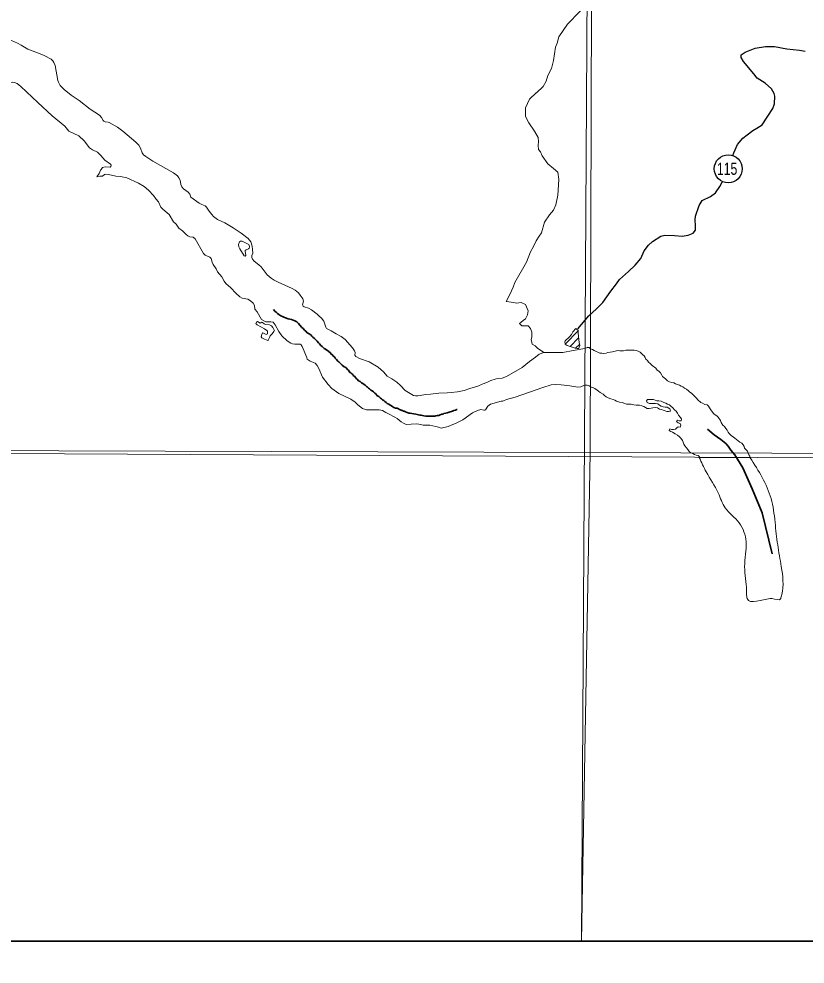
# Model space of a CAD drawing. Extents: x -1643653 to 4543381, y 1624270 to 13878484.
# Drawn here: x 604258 to 608778, y 8895895 to 8901328 of the extents above; entities that cross this region are included whole.
import ezdxf
from ezdxf.enums import TextEntityAlignment as Align

# ---------------------------------------------------------------- set-up
doc = ezdxf.new("R2010")
doc.units = 0
doc.header["$LTSCALE"] = 200
doc.linetypes.add('LONG_DASH_SHORT_DASH', pattern=[9.9, 6, -1.2, 1.5, -1.2])
doc.layers.add('1', color=7, linetype='Continuous', lineweight=13)
doc.layers.add('6', color=7, linetype='Continuous', lineweight=13)

msp = doc.modelspace()

# ---------------------------------------------------------------- linework, layer by layer
at = {"layer": '1', "lineweight": 25}
msp.add_spline([(814781, 9009175.5), (814787.2, 9009173.4), (814796.9, 9009173.4), (814799.4, 9009172.4), (814805.1, 9009174.5), (814805.6, 9009176.5), (814811.7, 9009179.5), (814811.7, 9009179.5), (814801.5, 9009181), (814790.7, 9009181.5), (814784.1, 9009183.1), (814777.4, 9009185.1), (814778.4, 9009175.5)], degree=3, dxfattribs=at)
at = {"layer": '6'}
for p, q in [((607398.2, 8899458.9), (607473.3, 8899534)), ((607427.1, 8899445.4), (607476, 8899494.2)), ((607458.9, 8899434.7), (607481.1, 8899456.9)), ((608462.4, 8898805.8), (608169.4, 8898807.8))]:
    msp.add_line(p, q, dxfattribs=at)
at = {"layer": '6', "lineweight": 35}
msp.add_lwpolyline([(574695.3, 8924769.6), (626625.7, 8924769.6), (626625.7, 8896026.7), (574695.3, 8896026.7)], close=True, dxfattribs=at)
at = {"layer": '6'}
for points in [[(607657.7, 8924743.3), (607574.2, 8909874.9), (607492.3, 8896026.7)], [(607518.6, 8901403.9), (607482.1, 8901370.7), (607412.3, 8901297.6), (607362.4, 8901224.5), (607352.5, 8901188), (607342.5, 8901164.7), (607332.5, 8901088.4), (607319.2, 8901041.9), (607299.3, 8901002), (607289.3, 8900968.8), (607272.7, 8900938.9), (607233.9, 8900903.3)], [(603607.9, 8901202.5), (603628.6, 8901215.9), (603671.7, 8901230.7), (603774.9, 8901247.2), (603862.9, 8901251.2), (603892.8, 8901248.7), (603993.8, 8901227), (604022.6, 8901225.8), (604073.7, 8901229.1), (604097.1, 8901225.2), (604136.5, 8901210.6), (604149.3, 8901209.6), (604198.3, 8901211), (604250.4, 8901188.4), (604270.6, 8901176.9)], [(604270.6, 8901176.9), (604309.9, 8901154.5), (604339.3, 8901141.9), (604370.9, 8901131.4)], [(604370.9, 8901131.4), (604370.9, 8901131.4), (604403.6, 8901117.1), (604442.5, 8901095.2), (604452, 8901087.1), (604458.6, 8901076.9), (604465.4, 8901060), (604482, 8900973.9), (604485.2, 8900964.1), (604495.8, 8900945.5), (604517.3, 8900922.7), (604558.5, 8900888.9), (604603.8, 8900858.4), (604667, 8900809.4), (604720.7, 8900774.8), (604733.1, 8900760.8), (604741.5, 8900744.4), (604745.2, 8900740.3), (604753.2, 8900735.9), (604770.9, 8900734.2), (604776.8, 8900732.2), (604824.3, 8900704.6), (604854.7, 8900681.5), (604929.1, 8900620.1), (604947.7, 8900602.6), (604957.6, 8900585), (604966.3, 8900557.4), (604974.2, 8900547), (604987.4, 8900535.9), (605027.8, 8900510.6), (605147.2, 8900442.4), (605169.2, 8900426.4), (605178, 8900414.5), (605184.6, 8900400), (605189.5, 8900375.3), (605194.2, 8900361.7), (605203.3, 8900351.7), (605231.7, 8900331.2), (605239.8, 8900319.8), (605246.1, 8900303.3), (605294.8, 8900269.1), (605308.7, 8900261.3), (605318.4, 8900257.2)], [(604366, 8900847), (604269.1, 8900939.9), (604248, 8900956), (604232.7, 8900962.7), (604218.8, 8900964.1), (604182.6, 8900956.3), (604161.8, 8900955.6), (604125.6, 8900973.4), (604104.3, 8900978.3), (604083.2, 8900978.5), (604062.8, 8900972.3)], [(607232.8, 8900902.4), (607193, 8900865.8), (607169.7, 8900816), (607169.7, 8900766.2), (607189.6, 8900729.7), (607222.9, 8900683.2), (607242.8, 8900646.7), (607246.1, 8900623.4), (607242.8, 8900600.2), (607246.1, 8900576.9), (607256.1, 8900563.6), (607266.1, 8900540.4), (607299.3, 8900493.9), (607332.5, 8900467.3), (607355.8, 8900447.4), (607362.4, 8900404.2), (607355.8, 8900314.6), (607345.8, 8900258.1), (607332.5, 8900228.2), (607309.3, 8900201.6), (607279.4, 8900158.5), (607262.7, 8900098.7), (607249.5, 8900078.8), (607232.8, 8900052.2), (607216.2, 8900019), (607199.6, 8899989.1), (607176.3, 8899929.3), (607109.9, 8899813.1), (607099.9, 8899786.5), (607080, 8899743.3), (607060, 8899703.5), (607103.2, 8899696.8), (607119.8, 8899693.5), (607146.4, 8899696.8), (607169.7, 8899686.9), (607186.3, 8899650.3), (607183, 8899627.1), (607169.7, 8899603.8), (607156.4, 8899593.9), (607146.4, 8899583.9), (607136.5, 8899577.3), (607149.8, 8899564), (607186.3, 8899564), (607199.6, 8899547.4), (607206.2, 8899527.4), (607206.2, 8899507.5), (607206.2, 8899497.6), (607202.9, 8899484.3), (607206.2, 8899467.7), (607209.6, 8899457.7), (607226.2, 8899447.8), (607239.5, 8899434.5), (607276, 8899411.2)], [(604545.7, 8900683.2), (604522.7, 8900710.9), (604449.6, 8900771.1), (604366, 8900847)], [(604745.3, 8900474.6), (604755.6, 8900477.1), (604782.2, 8900475.7), (604787.1, 8900478.4), (604787.9, 8900487.3), (604784.5, 8900492.2), (604752, 8900515.1), (604729.6, 8900542.8), (604709.4, 8900561), (604681.6, 8900575), (604663.6, 8900587.3), (604633.8, 8900627.5), (604602, 8900655.7), (604545.7, 8900683.2)], [(604706.6, 8900419.8), (604719.1, 8900439.6), (604727.3, 8900457.6), (604729.9, 8900461.2), (604729.9, 8900461.2)], [(604729.9, 8900461.2), (604737.9, 8900472.8), (604745.3, 8900474.6)], [(605045.3, 8900294.2), (605031, 8900312.3), (605003.2, 8900342.6), (604977.4, 8900365.2), (604945.5, 8900383.7), (604877.4, 8900413.4), (604842.3, 8900421.4), (604815.8, 8900423.5), (604773.8, 8900433.3), (604754.4, 8900435.3), (604749.3, 8900433), (604738.7, 8900423.7), (604723, 8900423.6), (604706.6, 8900419.8)], [(605438.8, 8899820.5), (605424.5, 8899844.7), (605400.3, 8899874.5), (605391.9, 8899891.1), (605374.3, 8899916.5), (605368.7, 8899929), (605362.7, 8899950.1), (605355.1, 8899957.3), (605329.3, 8899970.5), (605318.8, 8899978.5), (605271.5, 8900063.6), (605260.1, 8900073.8), (605241.3, 8900075.8), (605228.1, 8900080.5), (605218.7, 8900087.6), (605197.7, 8900109.2), (605177.8, 8900125.6), (605161.6, 8900148.5), (605147.3, 8900162.1), (605121.1, 8900202.5), (605110.9, 8900213.2), (605084.9, 8900233.7), (605074.1, 8900246.2), (605060.1, 8900275.4), (605045.3, 8900294.2)], [(605318.4, 8900257.2), (605328.1, 8900253.2), (605335.8, 8900246.2), (605350.9, 8900222.8), (605366.1, 8900202.7), (605377.3, 8900192.3), (605399.9, 8900175.6), (605442.3, 8900156.2), (605489.3, 8900126.6)], [(605489.3, 8900126.6), (605536.4, 8900097), (605576.3, 8900065.9), (605584, 8900055.8)], [(605584, 8900055.8), (605591.8, 8900045.6), (605599.5, 8900021.8), (605601.3, 8900001.9)], [(605601.3, 8900001.9), (605603.1, 8899982.1), (605597.9, 8899967.5), (605596.6, 8899957), (605600.2, 8899946.1), (605609.6, 8899935.7), (605637, 8899914.4), (605637, 8899914.4), (605649.8, 8899902), (605684.5, 8899857.5), (605707.9, 8899837.1), (605725.2, 8899825.1), (605748.8, 8899814.5)], [(605651.9, 8899599.2), (605627.2, 8899644.2), (605614.9, 8899659.3), (605613, 8899680), (605604.8, 8899694.2), (605588.8, 8899707.8), (605573.8, 8899716.3), (605540.9, 8899723.1), (605528.7, 8899729.8), (605504.9, 8899751.3), (605476.1, 8899781.6), (605446.9, 8899806.9), (605438.8, 8899820.5)], [(605748.8, 8899814.5), (605828.9, 8899778.6), (605845.6, 8899768.4), (605864.6, 8899753.2), (605875.9, 8899739.1)], [(605875.9, 8899739.1), (605887.1, 8899725), (605890.8, 8899718.1), (605893.6, 8899706.3), (605887.9, 8899684.9), (605892.5, 8899676.5), (605897.1, 8899672.9), (605922.3, 8899665.2), (605940.2, 8899656.1), (605972.7, 8899630.7), (605982.6, 8899621.7)], [(605800.4, 8899478.3), (605768.7, 8899506.2), (605752.1, 8899530.8), (605730.5, 8899570.1), (605719.2, 8899583.9), (605706, 8899587.4), (605690.9, 8899586.3), (605677.8, 8899587.4), (605651.9, 8899599.2)], [(605982.6, 8899621.7), (605997.9, 8899607.7), (606011.1, 8899590.2), (606021.8, 8899555.1), (606026.3, 8899548.7), (606053.9, 8899535.2), (606082.6, 8899518.2)], [(605886.8, 8899444.2), (605880.5, 8899454.1), (605875.6, 8899458), (605871.8, 8899459), (605843.6, 8899457.8), (605831.8, 8899459.6), (605821.4, 8899464.6), (605800.4, 8899478.3)], [(606082.6, 8899518.2), (606110.4, 8899501.7), (606133.8, 8899485.1), (606175, 8899438.1), (606188.2, 8899420.1), (606191.5, 8899410.3), (606189.5, 8899394.8), (606194.9, 8899386.7), (606215.6, 8899376.8), (606270.9, 8899356.2), (606324.1, 8899326.3), (606339, 8899313.3)], [(606167, 8899141.3), (606097.8, 8899173.8), (606057.4, 8899203.2), (606036.3, 8899225.7), (606003.4, 8899268.5), (605982, 8899319.3), (605972.7, 8899335.8), (605960.9, 8899348.2), (605932.8, 8899360.8), (605920.3, 8899368.7), (605916, 8899369.4), (605914.2, 8899381.2), (605886.8, 8899444.2)], [(606996.3, 8899256.7), (607009.1, 8899260.5), (607037.2, 8899263), (607061.2, 8899271.7), (607150.5, 8899324.7), (607193.7, 8899358.8), (607228.5, 8899383), (607248.7, 8899401.6), (607276, 8899411.2), (607305.9, 8899411.2), (607385.7, 8899411.2), (607445.5, 8899421.2), (607512.3, 8899432.5)], [(607512.3, 8899432.5), (607525.9, 8899438.3), (607537.1, 8899438.2), (607545.2, 8899432.1), (607555.3, 8899427.9), (607565.5, 8899422.8), (607577.6, 8899416.6), (607586.8, 8899411.4), (607597.9, 8899407.3), (607609.1, 8899406.2), (607621.3, 8899405.1), (607633.5, 8899406), (607643.7, 8899410), (607658, 8899413), (607671.2, 8899413.9), (607701.8, 8899420.9), (607713, 8899420.8), (607723.1, 8899420.7), (607734.3, 8899420.7), (607747.6, 8899424.6), (607757.7, 8899424.6), (607770, 8899424.5), (607783.2, 8899424.4), (607795.4, 8899424.3), (607806.6, 8899422.2), (607817.7, 8899418.1), (607830.9, 8899411.9), (607838, 8899404.7), (607846.1, 8899397.5), (607853.1, 8899390.3)], [(607853.1, 8899390.3), (607858.2, 8899381.2), (607863.2, 8899371.9), (607871.3, 8899363.7), (607878.3, 8899355.6), (607887.4, 8899347.3), (607899.6, 8899336.1), (607919.8, 8899319.6), (607927.8, 8899309.4), (607937, 8899302.2), (607946, 8899293), (607954.1, 8899280.7), (607959.1, 8899271.5), (607975.3, 8899258.1), (607987.4, 8899247.9), (607998.6, 8899242.7), (608011.8, 8899238.6), (608023, 8899235.4), (608033.1, 8899230.3), (608045.3, 8899226.1), (608056.4, 8899222), (608065.6, 8899217.8), (608075.7, 8899212.7), (608085.8, 8899205.5), (608097, 8899199.3), (608108.1, 8899190.1), (608116.2, 8899182.9), (608124.3, 8899176.7), (608135.4, 8899166.4), (608142.5, 8899159.3), (608154.6, 8899148), (608160.6, 8899137.8), (608178.8, 8899123.4), (608189, 8899119.2), (608202.2, 8899112), (608214.3, 8899108.9), (608222.4, 8899101.7), (608228.5, 8899092.5), (608236.5, 8899081.2), (608246.6, 8899067.9), (608252.7, 8899058.7), (608260.8, 8899052.6), (608269.9, 8899046.4), (608279, 8899038.2), (608291, 8899018.7), (608295, 8899007.5), (608306.1, 8898992.2), (608314.2, 8898985), (608322.3, 8898973.7), (608329.3, 8898963.5), (608335.3, 8898953.3), (608342.4, 8898945.1), (608352.5, 8898933.8), (608365.7, 8898923.5), (608374.8, 8898918.4), (608383.9, 8898910.2), (608393, 8898903), (608403.1, 8898895.8), (608414.2, 8898889.6), (608421.3, 8898880.4), (608427.3, 8898870.2), (608430.3, 8898859.9), (608439.4, 8898850.7), (608447.5, 8898843.5), (608451.5, 8898832.3)], [(606339, 8899313.3), (606353.8, 8899300.2), (606375.8, 8899273.6), (606401.3, 8899259.5), (606425.6, 8899243.5), (606430.3, 8899239.2)], [(606430.3, 8899239.2), (606451.1, 8899220.5), (606477.9, 8899191.6), (606526.1, 8899162.9), (606538.8, 8899160.4), (606552.3, 8899160.9), (606564.8, 8899163.4)], [(606850.9, 8899202.7), (606897.3, 8899217.3), (606921.3, 8899228.2), (606948.9, 8899237.7), (606970.8, 8899249.3), (606996.3, 8899256.7)], [(607510.3, 8899223.4), (607489.5, 8899213.8), (607472.3, 8899210.6), (607425.7, 8899218.6), (607376, 8899224.9), (607343.2, 8899226.9), (607318.7, 8899223.8), (607269.6, 8899209.6), (607112, 8899153.1), (607061.6, 8899139.4), (607044.9, 8899132.1), (607038.2, 8899131.2)], [(607965.2, 8899123.7), (607951, 8899129.9), (607937.8, 8899133.1), (607926.6, 8899133.2), (607916.5, 8899137.3), (607906.3, 8899140.4), (607892.1, 8899140.5), (607872.8, 8899140.6), (607866.6, 8899132.5), (607870.6, 8899122.3), (607882.8, 8899117.1), (607894, 8899117.1), (607904.2, 8899117), (607917.4, 8899116.9), (607930.6, 8899115.8), (607940.7, 8899107.6), (607950.8, 8899101.4), (607963, 8899097.3), (607974.2, 8899096.2), (607984.4, 8899096.1), (607999.6, 8899085.8), (608003.5, 8899073.6), (607993.3, 8899070.6), (607983.2, 8899070.6), (607973, 8899074.8), (607961.9, 8899078.9), (607952.7, 8899083.1), (607941.6, 8899084.2), (607930.4, 8899092.4), (607917.2, 8899093.5), (607903, 8899092.6), (607892.8, 8899089.6), (607881.6, 8899088.6), (607870.4, 8899088.7), (607861.3, 8899093.8), (607850.1, 8899100), (607840, 8899104.2), (607826.8, 8899108.3), (607816.6, 8899108.4), (607806.4, 8899108.4), (607793.2, 8899109.6), (607778, 8899112.7), (607763.7, 8899113.8), (607751.5, 8899113.9), (607741.4, 8899118), (607727.2, 8899122.2), (607712, 8899125.3), (607693.7, 8899131.6), (607684.6, 8899136.7), (607674.4, 8899139.9), (607661.2, 8899144), (607646, 8899150.2), (607634.8, 8899155.4), (607625.7, 8899163.6), (607617.7, 8899170.8), (607600.4, 8899180.1), (607591.3, 8899188.3), (607583.2, 8899194.4), (607569.1, 8899203.7), (607557.9, 8899208.9), (607547.8, 8899212), (607536.6, 8899218.2), (607525.4, 8899222.3), (607515.3, 8899222.4), (607510.3, 8899223.4)], [(606564.8, 8899163.4), (606594.8, 8899169.2), (606624, 8899170.2), (606673, 8899176.3), (606719.7, 8899178.1), (606743.5, 8899180.8)], [(606743.5, 8899180.8), (606780.2, 8899185.1), (606817.4, 8899192.1), (606850.9, 8899202.7)], [(606368.4, 8899065.7), (606348.9, 8899077), (606329, 8899080.2), (606255.6, 8899080.9), (606233.8, 8899088.8), (606207, 8899108.8), (606191.6, 8899125.1), (606167, 8899141.3)], [(607038.2, 8899131.2), (607030.1, 8899130.2), (606968.5, 8899113.9), (606953.5, 8899101.6), (606940.8, 8899080.5), (606936.9, 8899079.8)], [(608076.6, 8898895.8), (608072.6, 8898905), (608064.5, 8898918.3), (608056.4, 8898925.5), (608045.3, 8898934.7), (608031.1, 8898943), (608015.9, 8898952.2), (608006.8, 8898956.4), (607996.7, 8898961.5), (607999.8, 8898971.7), (608011, 8898968.6), (608022.1, 8898968.5), (608032.3, 8898969.5), (608040.5, 8898976.5), (608048.7, 8898982.6), (608060.9, 8898981.5), (608064, 8898992.7), (608059, 8899001.9), (608048.8, 8899007.1), (608039.7, 8899013.2), (608043.9, 8899022.4), (608054, 8899017.2), (608066.2, 8899017.1), (608067.3, 8899029.3), (608059.2, 8899038.6), (608051.2, 8899049.8), (608044.1, 8899061.1), (608036.1, 8899072.3), (608027, 8899080.5), (608017.9, 8899092.8), (608005.8, 8899102.1), (607997.7, 8899110.3), (607987.5, 8899113.4), (607977.4, 8899119.6), (607965.2, 8899123.7)], [(606669.7, 8898980.5), (606654.6, 8898985.8), (606620, 8898992.5), (606583.1, 8898992.2), (606556.5, 8898999.1), (606542.7, 8899000.4), (606485.3, 8898997.2), (606468.8, 8899003.8), (606455.3, 8899011.8), (606432, 8899031.1), (606419.7, 8899039.2), (606382.7, 8899057.4), (606368.4, 8899065.7)], [(606936.9, 8899079.8), (606931.9, 8899079.1), (606913.4, 8899083.4), (606894.4, 8899077.1), (606866.6, 8899063), (606810.7, 8899023.7), (606776, 8899005.8), (606726.3, 8898985.3), (606684.8, 8898975.2), (606669.7, 8898980.5)], [(574695.3, 8898953.2), (596544.3, 8898870.4), (626625.7, 8898710.8)], [(608169.4, 8898807.8), (608170.6, 8898811.7), (608162.5, 8898818.9), (608151.3, 8898821), (608142.2, 8898825.1), (608132.1, 8898829.2), (608120.9, 8898833.4), (608110.8, 8898841.6), (608104.8, 8898852.9), (608096.7, 8898862.1), (608087.6, 8898873.3), (608081.6, 8898882.6), (608076.6, 8898895.8)], [(608451.5, 8898832.3), (608454.5, 8898822.1), (608460.5, 8898813.9), (608462.4, 8898805.8), (608169.4, 8898807.8)]]:
    msp.add_lwpolyline(points, dxfattribs=at)
for points in [[(618535.2, 8909853.3), (607574.3, 8909890.7), (607543.3, 8898835.3), (618504.2, 8898795.8)], [(605578, 8900006.4), (605581.1, 8900009.7), (605583.1, 8900017.2), (605581.8, 8900027.9), (605579.6, 8900031.9), (605553.8, 8900045.2), (605540.6, 8900049.4), (605532.2, 8900049.6), (605526.5, 8900045.7), (605520.9, 8900031.3), (605522.3, 8900018.3), (605527.3, 8900006.6), (605552.8, 8899966.1), (605559, 8899963.9), (605562.7, 8899968.7), (605558.6, 8899992.7), (605559.4, 8899996.8), (605563.9, 8900000.6)], [(605726.5, 8899537.9), (605724, 8899530.6), (605714.4, 8899518.2), (605703, 8899506.1), (605697.8, 8899496.6), (605691.8, 8899481.5), (605690, 8899479.8), (605670.7, 8899486.1), (605654.2, 8899494.3), (605651.4, 8899501.1), (605654.2, 8899514.3), (605658.7, 8899522.5), (605659.8, 8899523), (605664.4, 8899521.9), (605680, 8899513.5), (605686.4, 8899518), (605687.1, 8899532.4), (605682.6, 8899537.5), (605669, 8899546.2), (605627.1, 8899569.7), (605621, 8899577.3), (605624.1, 8899584.8), (605629.5, 8899588.5), (605644.9, 8899579.4), (605648.7, 8899580.6), (605650.3, 8899583.7), (605653.3, 8899585.6), (605658.1, 8899583.4), (605667.7, 8899575.2), (605676.3, 8899570.6), (605698.8, 8899568.8), (605709.7, 8899562.8), (605717.5, 8899553.2), (605726.3, 8899538.9)], [(607460.5, 8899548.4), (607473.4, 8899537.4), (607473.1, 8899520.7), (607479, 8899466.9), (607482.5, 8899450.2), (607481.5, 8899443.7), (607477.8, 8899435.1), (607475, 8899432.4), (607467.5, 8899432.5), (607456.8, 8899435.3), (607411.1, 8899450.8), (607397.8, 8899459.1), (607396.2, 8899472.7), (607398.9, 8899476.5), (607421.7, 8899498.1), (607434.4, 8899514.6), (607443.2, 8899529)], [(596544.3, 8898870.4), (596531.7, 8896026.7), (607492.3, 8896026.7), (607543.3, 8898835.3)]]:
    msp.add_lwpolyline(points, close=True, dxfattribs=at)
at = {"layer": '6', "lineweight": 25}
for points in [[(608362.5, 8900541.9), (608368.2, 8900558.4), (608389.8, 8900605.2), (608420.5, 8900642.9), (608446, 8900662.2), (608477.7, 8900686.6), (608500.2, 8900699.8), (608531.8, 8900719.1), (608592.3, 8900811.7), (608601.6, 8900840.2), (608604.8, 8900883), (608599.7, 8900899.3), (608584.6, 8900924.8), (608548, 8900957.4), (608502.2, 8900986.1), (608484, 8901011.6), (608424.2, 8901083), (608411, 8901106.4), (608410, 8901120.7), (608433.5, 8901137), (608490.7, 8901160.3), (608550.8, 8901168.3), (608602.8, 8901168.2), (608674, 8901155.9), (608745.3, 8901147.6), (608778.9, 8901141.4)], [(607472.2, 8899545.8), (607534.4, 8899621.6), (607579.4, 8899661.2), (607616.2, 8899696.8), (607661.2, 8899761.9), (607694, 8899804.7), (607711.4, 8899829.1), (607763.6, 8899875.9), (607801.4, 8899912.5), (607833.1, 8899950.1), (607852.6, 8899993.9), (607877.2, 8900026.4), (607900.7, 8900048.8), (607948.7, 8900079.3), (607972.2, 8900084.3), (608027.2, 8900083.2), (608072, 8900078.1), (608106.7, 8900084.1), (608135.2, 8900096.3), (608147.5, 8900113.6), (608148.6, 8900139), (608146.7, 8900173.7), (608147.8, 8900194.1), (608168.4, 8900255.2), (608186.9, 8900283.6), (608234.8, 8900306), (608263.4, 8900327.3), (608288, 8900363.9), (608301.4, 8900388.4), (608303.7, 8900393.1)]]:
    msp.add_lwpolyline(points, dxfattribs=at)
at = {"layer": '6', "linetype": 'LONG_DASH_SHORT_DASH', "lineweight": 35}
for points in [[(605956.8, 8899491.3), (605948.6, 8899499.4), (605941.5, 8899504.1), (605935.9, 8899511.2), (605923.7, 8899519.4), (605916, 8899524), (605907.9, 8899532.7), (605899.8, 8899538.3), (605891.6, 8899548.5), (605884.5, 8899554.7), (605873.3, 8899567.4), (605865.1, 8899577.7), (605855, 8899586.9), (605844.3, 8899592), (605825.4, 8899599.7), (605805.6, 8899603.2), (605791.3, 8899609.4), (605781.7, 8899613.5), (605773, 8899617.5), (605763.3, 8899621.6), (605758.2, 8899625.7), (605751.6, 8899628.8), (605744.5, 8899635.4), (605736.9, 8899643.1), (605728.7, 8899648.2), (605721.2, 8899657.3)], [(606202.1, 8899256.6), (606197.1, 8899261.7), (606188.4, 8899272.5), (606181.8, 8899277.1), (606178.2, 8899283.7), (606171.1, 8899287.3), (606167, 8899293.9), (606159.4, 8899298), (606155.3, 8899306.2), (606148.2, 8899311.3), (606137, 8899323.6), (606127.3, 8899328.2), (606117.1, 8899337.9), (606108, 8899345.6), (606097.3, 8899355.8), (606091.2, 8899361.4), (606084, 8899370.1), (606076.9, 8899377.8), (606072.3, 8899385.4), (606065.2, 8899389.5), (606061.1, 8899397.2), (606054, 8899400.8), (606046.9, 8899410.5), (606039.7, 8899414.1), (606035.2, 8899420.2), (606028, 8899423.8), (606020.9, 8899430.4), (606013.8, 8899434), (606005.6, 8899440.7), (606001.1, 8899444.8), (605993.4, 8899450.9), (605985.8, 8899460.1), (605980.7, 8899465.7), (605973.1, 8899474.9), (605968.5, 8899480), (605961.3, 8899486.7), (605956.8, 8899491.3)], [(606696.3, 8899056.2), (606688.7, 8899055.7), (606679.1, 8899051.6), (606671.4, 8899049.1), (606662.8, 8899047.5), (606654.6, 8899046), (606649, 8899045), (606641.9, 8899044), (606630.2, 8899044), (606622.6, 8899044), (606614.4, 8899044), (606609.8, 8899044), (606602.2, 8899044.5), (606596.6, 8899045), (606586.9, 8899046.5), (606578.3, 8899048.1), (606570.1, 8899049.6), (606562.5, 8899051.1), (606554.9, 8899052.7), (606548.3, 8899054.2), (606540.1, 8899055.7), (606528.4, 8899057.2), (606517.7, 8899060.3), (606508.1, 8899061.8), (606498.9, 8899061.8), (606490.8, 8899065.9), (606481.1, 8899069.5), (606472.9, 8899072.6), (606468.9, 8899073.6), (606462.8, 8899076.7), (606458.7, 8899077.7), (606451.1, 8899081.3), (606446.5, 8899082.3), (606439.8, 8899086.4), (606432.2, 8899090), (606423.6, 8899090.5), (606414.4, 8899094.1), (606408.3, 8899097.6), (606400.7, 8899103.8), (606392.5, 8899106.8), (606384.4, 8899113.5), (606375.7, 8899116.6), (606370.1, 8899122.7), (606362.5, 8899127.8), (606355.4, 8899133.9), (606347.7, 8899138), (606342.6, 8899144.7), (606336, 8899148.8), (606326.8, 8899156.9), (606316.7, 8899162.6), (606311.6, 8899171.8), (606304, 8899176.4), (606297.3, 8899183.5), (606288.2, 8899190.7), (606281.6, 8899194.8), (606273.4, 8899202.4), (606268.3, 8899205.5), (606260.2, 8899212.2), (606255.6, 8899215.2), (606248, 8899222.9), (606236.2, 8899232.6), (606227.6, 8899235.2), (606219.4, 8899243.3), (606211.3, 8899247.4), (606202.1, 8899256.6)], [(606776.9, 8899082.3), (606776.7, 8899082.3), (606768.6, 8899079.2), (606759.4, 8899076.2), (606750.8, 8899073.6), (606731.5, 8899067.5), (606720.8, 8899063.9), (606711.6, 8899061.3), (606701.9, 8899060.3), (606696.3, 8899056.2)], [(608589.7, 8898253.2), (608531.8, 8898489.6), (608473.8, 8898626.9), (608419.7, 8898746.8), (608375.2, 8898822.2), (608352, 8898849.2), (608336.5, 8898872.3), (608323.3, 8898886.6), (608292.9, 8898910.1), (608256.3, 8898937.7), (608216.7, 8898970.6)]]:
    msp.add_lwpolyline(points, dxfattribs=at)
at = {"layer": '6', "lineweight": 25}
msp.add_circle((608336.3, 8900466.1), 80.3, dxfattribs=at)
at = {"layer": '6'}
msp.add_spline([(608169.4, 8898807.8), (608210, 8898723.6), (608278.8, 8898603.2), (608318.9, 8898517.3), (608399.1, 8898431.3), (608439.2, 8898322.4), (608430.6, 8898179.2), (608442.1, 8898044.5), (608442.1, 8898015.4), (608445, 8897995.8), (608576.8, 8897995.8), (608588.2, 8897995.8), (608638.5, 8897995.8), (608640.5, 8898005.2), (608644.2, 8898020.1), (608641.5, 8898180.1), (608620.8, 8898304.5), (608605.4, 8898434.2), (608582.5, 8898571.7), (608462.4, 8898805.8)], degree=3, dxfattribs=at)

# ---------------------------------------------------------------- texts
at = {"layer": '6', "width": 0.75}
msp.add_text('115', height=70, dxfattribs=at).set_placement((608329.9, 8900431.4), align=Align.CENTER)

doc.saveas('drawing.dxf')
